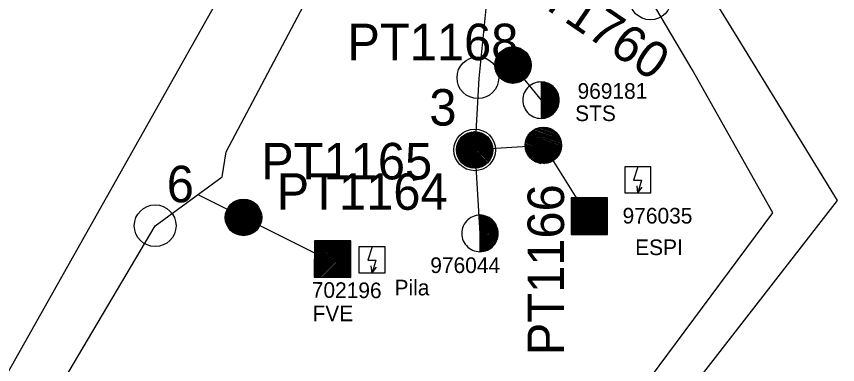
# Model space of a CAD drawing. Extents: x -788977 to -785292, y -1155262 to -1151579.
# Drawn here: x -787986 to -787198, y -1154312 to -1153978 of the extents above; entities that cross this region are included whole.
import ezdxf

# ---------------------------------------------------------------- set-up
doc = ezdxf.new("R2010")
doc.units = 0
for name, color, linetype in [('Default', 7, 'Continuous'), ('Vrstva 1', 7, 'Continuous'), ('Vrstva 2', 7, 'Continuous'), ('Vrstva 3', 7, 'Continuous'), ('Vrstva 4', 7, 'Continuous'), ('Vrstva 47', 7, 'Continuous'), ('Vrstva 5', 7, 'Continuous')]:
    doc.layers.add(name, color=color, linetype=linetype)

# ---------------------------------------------------------------- blocks, each defined once
blk = doc.blocks.new('PS700')
at = {"layer": 'Vrstva 47'}
for points in [[(12.48, 12.51), (-12.52, 12.51)], [(-12.52, 12.51), (-12.52, -12.49)], [(-0.02, 12.51), (-3.96, -0.19)], [(12.48, -12.49), (12.48, 12.51)], [(-3.96, -0.19), (3.52, -0.19)], [(-0.02, -12.49), (-0.71, -5.7)], [(3.52, -0.19), (-0.02, -12.49)], [(-0.02, -12.49), (4.31, -7.08)], [(-12.52, -12.49), (12.48, -12.49)]]:
    blk.add_lwpolyline(points, dxfattribs=at)
blk = doc.blocks.new('PS100')
at = {"layer": 'Default'}
for p, q in [((-17.47, -0.71), (0.71, 17.47)), ((-17.47, 0.7), (-0.7, 17.47)), ((-17.37, -2.02), (2.02, 17.37)), ((-17.34, 2.25), (-2.25, 17.34)), ((-17.18, -3.25), (3.25, 17.18)), ((-17.03, 3.97), (-3.97, 17.03)), ((-16.92, -4.41), (4.41, 16.92)), ((-16.6, -5.5), (5.5, 16.6)), ((-16.43, 5.99), (-5.99, 16.43)), ((-16.22, -6.53), (6.53, 16.22)), ((-15.79, -7.52), (7.52, 15.79)), ((-15.31, -8.45), (8.45, 15.31)), ((-15.22, 8.61), (-8.61, 15.22)), ((-14.78, -9.34), (9.34, 14.78)), ((-14.22, -10.18), (10.18, 14.22)), ((-13.6, -10.99), (10.99, 13.6)), ((-12.95, -11.75), (11.75, 12.95)), ((-12.26, -12.47), (12.47, 12.26)), ((-11.53, -13.15), (13.15, 11.53)), ((-10.75, -13.79), (13.79, 10.75)), ((-9.94, -14.39), (14.39, 9.94)), ((-9.08, -14.95), (14.95, 9.08)), ((-8.18, -15.46), (15.46, 8.18)), ((-7.23, -15.92), (15.92, 7.23)), ((-6.23, -16.34), (16.34, 6.23)), ((-5.18, -16.7), (16.7, 5.18)), ((-4.07, -17.01), (17.01, 4.07)), ((-2.89, -17.25), (17.25, 2.89)), ((-1.64, -17.41), (17.41, 1.64)), ((-0.3, -17.48), (17.48, 0.3)), ((1.15, -17.45), (17.45, -1.15)), ((2.74, -17.27), (17.27, -2.74)), ((4.54, -16.89), (16.89, -4.54)), ((6.68, -16.16), (16.16, -6.68)), ((9.71, -14.54), (14.54, -9.71))]:
    blk.add_line(p, q, dxfattribs=at)
blk.add_circle((0, 0), 17.49, dxfattribs=at)
blk = doc.blocks.new('PS140')
at = {"layer": 'Default'}
for p, q in [((-17.49, -0.01), (0.01, 17.49)), ((-17.43, -1.37), (1.37, 17.43)), ((-17.42, 1.47), (-1.47, 17.42)), ((-17.29, -2.63), (2.63, 17.29)), ((-17.21, 3.1), (-3.1, 17.21)), ((-17.06, -3.82), (3.82, 17.06)), ((-16.77, -4.95), (4.95, 16.77)), ((-16.77, 4.95), (-4.95, 16.77)), ((-16.42, -6.01), (6.01, 16.42)), ((-16.02, -7.02), (7.02, 16.02)), ((-15.93, 7.2), (-7.2, 15.93)), ((-15.56, -7.98), (7.98, 15.56)), ((-15.06, -8.89), (8.89, 15.06)), ((-14.51, -9.76), (9.76, 14.51)), ((-13.92, -10.58), (10.58, 13.92)), ((-13.75, 10.8), (-10.8, 13.75)), ((-13.29, -11.36), (11.36, 13.29)), ((-12.62, -12.11), (12.11, 12.62)), ((-11.91, -12.81), (12.81, 11.91)), ((-11.15, -13.47), (13.47, 11.15)), ((-10.36, -14.09), (14.09, 10.36)), ((-9.52, -14.67), (14.67, 9.52)), ((-8.64, -15.2), (15.2, 8.64)), ((-7.72, -15.69), (15.69, 7.72)), ((-6.74, -16.13), (16.13, 6.74)), ((-5.72, -16.52), (16.52, 5.72)), ((-4.64, -16.86), (16.86, 4.64)), ((-3.5, -17.13), (17.13, 3.5)), ((-2.29, -17.34), (17.34, 2.29)), ((-1, -17.46), (17.46, 1)), ((0.39, -17.48), (17.48, -0.39)), ((1.91, -17.38), (17.38, -1.91)), ((3.59, -17.11), (17.11, -3.59)), ((5.53, -16.59), (16.59, -5.53)), ((7.96, -15.57), (15.57, -7.96))]:
    blk.add_line(p, q, dxfattribs=at)
blk.add_circle((0, 0), 17.49, dxfattribs=at)
blk = doc.blocks.new('PS800')
at = {"layer": 'Vrstva 2'}
blk.add_circle((0, -0.01), 20, dxfattribs=at)
blk = doc.blocks.new('PS611')
at = {"layer": 'Default'}
for p, q in [((0, 16.16), (1.27, 17.43)), ((0, 14.75), (2.54, 17.29)), ((0, 13.33), (3.75, 17.09)), ((0, 11.92), (4.86, 16.79)), ((0, 10.51), (5.93, 16.44)), ((0, 9.09), (6.95, 16.05)), ((0, 7.68), (7.9, 15.58)), ((0, 6.26), (8.83, 15.1)), ((0, 4.85), (9.69, 14.54)), ((0, 3.44), (10.52, 13.96)), ((0, 2.02), (11.3, 13.33)), ((0, 0.61), (12.05, 12.66)), ((0, -0.81), (12.76, 11.95)), ((0, -2.22), (13.42, 11.2)), ((0, -3.64), (14.05, 10.41)), ((0, -5.05), (14.62, 9.57)), ((0, -6.46), (15.17, 8.71)), ((0, -7.88), (15.65, 7.77)), ((0, -9.29), (16.1, 6.81)), ((0, -10.71), (16.49, 5.79)), ((0, -12.12), (16.83, 4.71)), ((0, -13.53), (17.12, 3.59)), ((0, -14.95), (17.32, 2.37)), ((0, -16.36), (17.44, 1.08)), ((0.29, -17.49), (17.48, -0.29)), ((1.78, -17.41), (17.4, -1.79)), ((3.46, -17.15), (17.14, -3.46)), ((5.36, -16.66), (16.65, -5.37)), ((7.78, -15.65), (15.64, -7.79))]:
    blk.add_line(p, q, dxfattribs=at)
for points in [[(17.5, 0), (17.4, 1.83), (17.12, 3.64), (16.64, 5.4), (15.98, 7.11), (15.15, 8.75), (14.15, 10.28), (13, 11.71), (11.71, 13), (10.28, 14.15), (8.75, 15.15), (7.11, 15.98), (5.4, 16.64), (3.64, 17.12), (1.83, 17.4), (0, 17.5), (-1.83, 17.4), (-3.64, 17.12), (-5.41, 16.64), (-7.12, 15.98), (-8.75, 15.15), (-10.29, 14.15), (-11.71, 13), (-13.01, 11.71), (-14.16, 10.28), (-15.16, 8.75), (-15.99, 7.11), (-16.65, 5.4), (-17.12, 3.64), (-17.41, 1.83), (-17.5, 0), (-17.41, -1.83), (-17.12, -3.64), (-16.65, -5.41), (-15.99, -7.12), (-15.16, -8.75), (-14.16, -10.29), (-13.01, -11.71), (-11.71, -13.01), (-10.29, -14.16), (-8.75, -15.16), (-7.12, -15.99), (-5.41, -16.65), (-3.64, -17.12), (-1.83, -17.41), (0, -17.5), (1.83, -17.41), (3.64, -17.12), (5.4, -16.65), (7.12, -15.99), (8.75, -15.16), (10.28, -14.16), (11.71, -13.01), (13, -11.71), (14.15, -10.29), (15.15, -8.75), (15.98, -7.12), (16.64, -5.41), (17.12, -3.64), (17.4, -1.83), (17.5, 0)], [(0, 17.5), (0, -17.5)]]:
    blk.add_lwpolyline(points, dxfattribs=at)
blk = doc.blocks.new('PS631')
at = {"layer": 'Default'}
for p, q in [((-16.61, -14.95), (17.07, 18.74)), ((-16.61, -13.53), (15.66, 18.74)), ((-16.61, -12.12), (14.24, 18.74)), ((-16.61, -10.71), (12.83, 18.74)), ((-16.61, -9.29), (11.41, 18.74)), ((-16.61, -7.88), (10, 18.74)), ((-16.61, -6.46), (8.59, 18.74)), ((-16.61, -5.05), (7.17, 18.74)), ((-16.61, -3.63), (5.76, 18.74)), ((-16.61, -2.22), (4.34, 18.74)), ((-16.61, -0.81), (2.93, 18.74)), ((-16.61, 0.61), (1.51, 18.74)), ((-16.61, 2.02), (0.1, 18.74)), ((-16.61, 3.44), (-1.31, 18.74)), ((-16.61, 4.85), (-2.73, 18.74)), ((-16.61, 6.27), (-4.14, 18.74)), ((-16.61, 7.68), (-5.56, 18.74)), ((-16.61, 9.09), (-6.97, 18.74)), ((-16.61, 10.51), (-8.38, 18.74)), ((-16.61, 11.92), (-9.8, 18.74)), ((-16.61, 13.34), (-11.21, 18.74)), ((-16.61, 14.75), (-12.63, 18.74)), ((-16.61, 16.16), (-14.04, 18.74)), ((-16.61, 17.58), (-15.46, 18.74)), ((-16.51, -16.26), (18.39, 18.64)), ((-15.1, -16.26), (18.39, 17.22)), ((-13.69, -16.26), (18.39, 15.81)), ((-12.27, -16.26), (18.39, 14.39)), ((-10.86, -16.26), (18.39, 12.98)), ((-9.44, -16.26), (18.39, 11.57)), ((-8.03, -16.26), (18.39, 10.15)), ((-6.62, -16.26), (18.39, 8.74)), ((-5.2, -16.26), (18.39, 7.32)), ((-3.79, -16.26), (18.39, 5.91)), ((-2.37, -16.26), (18.39, 4.5)), ((-0.96, -16.26), (18.39, 3.08)), ((0.46, -16.26), (18.39, 1.67)), ((1.87, -16.26), (18.39, 0.25)), ((3.28, -16.26), (18.39, -1.16)), ((4.7, -16.26), (18.39, -2.58)), ((6.11, -16.26), (18.39, -3.99)), ((7.53, -16.26), (18.39, -5.4)), ((8.94, -16.26), (18.39, -6.82)), ((10.36, -16.26), (18.39, -8.23)), ((11.77, -16.26), (18.39, -9.65)), ((13.18, -16.26), (18.39, -11.06)), ((14.6, -16.26), (18.39, -12.48)), ((16.01, -16.26), (18.39, -13.89)), ((17.43, -16.26), (18.39, -15.3))]:
    blk.add_line(p, q, dxfattribs=at)
for points in [[(-16.61, 18.74), (-16.61, -16.26)], [(18.39, 18.74), (-16.61, 18.74)], [(-16.61, 18.74), (-16.61, -16.26)], [(18.39, -16.26), (18.39, 18.74)], [(-16.61, -16.26), (18.39, -16.26)]]:
    blk.add_lwpolyline(points, dxfattribs=at)

msp = doc.modelspace()

# ---------------------------------------------------------------- linework, layer by layer
at = {"layer": 'Vrstva 1'}
for points in [[(-787784.52, -1154107.93), (-787644.99, -1153844.16)], [(-787755.7, -1153896.58), (-788440.76, -1155112.99)], [(-787530.66, -1153919.1), (-787542.46, -1154037.84)], [(-787293.67, -1153999.52), (-787344.28, -1153917.25), (-787344.28, -1153917.25)], [(-787337.78, -1154029.03), (-787377.92, -1153961.53)], [(-787884.44, -1155057.87), (-787884.21, -1155057.43), (-787882.84, -1155055.2), (-787879.3, -1155051.45), (-787810.85, -1154955.57), (-787493.57, -1154533.63), (-787391.24, -1154402.66), (-787292.22, -1154275.24), (-787198.47, -1154154.71), (-787293.67, -1153999.52)], [(-787906.87, -1155037.07), (-787260.59, -1154166.71), (-787337.78, -1154029.03)], [(-787509.6, -1154025.43), (-787482.72, -1154058.55)], [(-787542.46, -1154037.84), (-787546.3, -1154106.23)], [(-787480.46, -1154101.91), (-787546.3, -1154106.23)], [(-787480.46, -1154101.91), (-787437.28, -1154171.02)], [(-787852.56, -1154178.96), (-787788.31, -1154132.05), (-787784.52, -1154107.93)], [(-787546.3, -1154106.23), (-787541.24, -1154186.34)], [(-787811.66, -1154149.1), (-787684.64, -1154212.69)], [(-788408.23, -1155117.78), (-787852.56, -1154178.96)]]:
    msp.add_lwpolyline(points, dxfattribs=at)

# ---------------------------------------------------------------- block references
at = {"layer": 'Vrstva 2'}
msp.add_blockref('PS140', (-787509.63, -1154024.95), dxfattribs=at)
for name, p, rotation in [('PS100', (-787480.46, -1154101.91), -64.12912780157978), ('PS140', (-787546.3, -1154106.23), 88.11831108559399), ('PS140', (-787767.9, -1154171), 50.33433061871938)]:
    msp.add_blockref(name, p, dxfattribs=dict(at, rotation=rotation))
at = {"layer": 'Vrstva 3'}
for name, p, rotation in [('PS611', (-787482.72, -1154058.55), 0.06103608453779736), ('PS631', (-787683.38, -1154212.21), -0.21757920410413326)]:
    msp.add_blockref(name, p, dxfattribs=dict(at, rotation=rotation))
for name, p in [('PS631', (-787437.28, -1154171.02)), ('PS611', (-787541.24, -1154186.34))]:
    msp.add_blockref(name, p, dxfattribs=at)
at = {"layer": 'Vrstva 4'}
for p, rotation in [((-787390, -1154135), 0.06180775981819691), ((-787644.68, -1154211.71), -0.0531993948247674)]:
    msp.add_blockref('PS700', p, dxfattribs=dict(at, rotation=rotation))
at = {"layer": 'Vrstva 5'}
for p, rotation in [((-787377.92, -1153961.53), 32.47125839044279), ((-787543.24, -1154037.03), 6.9489084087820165), ((-787546.3, -1154106.23), 88.11831108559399), ((-787852.56, -1154178.96), 39.06958899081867)]:
    msp.add_blockref('PS800', p, dxfattribs=dict(at, rotation=rotation))

# ---------------------------------------------------------------- texts
at = {"layer": 'Vrstva 2'}
for s, rotation, p in [('PT1760', 325.831, (-787511.33, -1153948.77)), ('PT1166', 90, (-787460.64, -1154303.13))]:
    msp.add_text(s, height=35, rotation=rotation, dxfattribs=at).set_placement(p)
for s, p in [('PT1168', (-787668.36, -1154020.21)), ('PT1165', (-787750.96, -1154134.52)), ('PT1164', (-787736.15, -1154163.67))]:
    msp.add_text(s, height=35, dxfattribs=at).set_placement(p)
at = {"layer": 'Vrstva 3'}
for s, p in [('969181', (-787447.72, -1154057.24)), ('STS', (-787450, -1154078.61)), ('976035', (-787404.55, -1154176.84)), ('ESPI', (-787392.51, -1154207.11)), ('976044', (-787588.86, -1154224.29)), ('Pila', (-787623.11, -1154245.77))]:
    msp.add_text(s, height=15, dxfattribs=at).set_placement(p)
for s, rotation, p in [('702196', 359.541, (-787702.51, -1154247.99)), ('FVE', 0.052, (-787701.71, -1154270.5))]:
    msp.add_text(s, height=15, rotation=rotation, dxfattribs=at).set_placement(p)
at = {"layer": 'Vrstva 5'}
for s, p in [('3', (-787589.76, -1154082.9)), ('6', (-787841.41, -1154156.43))]:
    msp.add_text(s, height=35, dxfattribs=at).set_placement(p)

doc.saveas('drawing.dxf')
